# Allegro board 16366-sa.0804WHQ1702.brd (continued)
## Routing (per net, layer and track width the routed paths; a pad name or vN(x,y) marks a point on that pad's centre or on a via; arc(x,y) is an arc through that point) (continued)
RESET_P12V_MB_IN: length 3.8
  TOP w0.178: U1.3 19.66,18.65 C19.1 R2.1 19.06,17.63 R1.2
RSVD0: length 11.3
  TOP w0.178: GF1.B30 42.65,7.97 45.12,12.27 TP6.1
RSVD1: length 12
  TOP w0.178: v1(31.65,8.9) 31.65,9.61 TP7.1
  BOTTOM w0.178: GF1.A19 v1(31.65,8.9)
S0_PCIE_SMCLK: length 26.4
  TOP w0.178: CN1.B5 26.29,29.78 26.29,29.37 26.09,29.17 20.75,29.17 19.43,27.85 17.2,27.85 14.81,30.23 14.81,40.19 15.68,41.06 15.68,41.46 15.68,41.62 15.67,41.64 15.97,41.94 RE1.1
S0_PCIE_SMDAT: length 27.8
  TOP w0.178: RE7.1 14.94,41.93 15.24,41.63 15.24,41.46 15.24,41.24 14.38,40.37 14.38,30.05 17.02,27.41 19.61,27.41 20.93,28.74 26.85,28.74 27.09,28.49 CN1.B6
S0_SMB_ALERT_B12_N: length 3.5
  TOP w0.178: RE4.1 CN1.B12
S0_SMB_CLK_A32: length 19
  TOP w0.178: CN1.A32 55.44,34.82 55.44,35.22 55.11,35.55 39.68,35.55 39.09,36.14 39.09,36.49 38.8,36.79 RE2.2
S0_SMB_DAT_A33: length 20.9
  TOP w0.178: CN1.A33 56.09,35.18 55.29,35.98 39.86,35.98 39.53,36.32 39.53,36.49 39.82,36.79 RE3.2
S1_PCIE_SMCLK: length 11.5
  TOP w0.178: CN2.B5 26.09,48.74 24.63,47.28 21.72,47.28 20.6,48.39 18.36,48.39 RE6.1
S1_PCIE_SMDAT: length 10.5
  TOP w0.178: RE8.1 18.06,47.71 18.32,47.96 20.42,47.96 21.54,46.85 24.81,46.85 26.4,48.43 26.94,48.98 27.09,48.98 CN2.B6
S1_SMB_ALERT_B12_N: length 6.5
  TOP w0.178: RE5.1 36.64,43.36 36.64,45.99 35.09,47.54 CN2.B12
S1_SMB_CLK_A32: length 32.9
  TOP w0.178: RE9.2 39.13,41.41 39.13,42.08 37.92,43.29 37.92,45.68 35.87,47.73 35.87,49.59 36.88,50.6 36.88,51.74 37.56,52.42 38.29,52.42 38.85,52.98 38.85,53.97 39.57,54.68 54.3,54.68 55.09,55.47 CN2.A32
S1_SMB_DAT_A33: length 33.2
  TOP w0.178: CN2.A33 56.09,53.47 55.31,54.25 54.48,54.25 54.48,54.25 39.75,54.25 39.29,53.79 39.29,52.8 38.47,51.99 37.74,51.99 37.31,51.56 37.31,50.42 36.3,49.41 36.3,47.91 38.35,45.85 38.35,43.47 39.56,42.26 39.56,41.41 RE10.2
S2_PCIE_SMCLK: length 5.3
  TOP w0.178: CN3.B5 26.09,69.59 25.77,69.27 25.77,67.92 25.42,67.57 RE12.1
S2_PCIE_SMDAT: length 3.5
  TOP w0.178: CN3.B6 27.09,69.97 26.2,69.09 26.2,67.92 26.56,67.57 RE13.1
S2_SMB_ALERT_B12_N: length 5.8
  TOP w0.178: RE11.1 37.3,66.62 35.09,68.83 CN3.B12
S2_SMB_CLK_A32: length 39.1
  TOP w0.178: CN3.A32 55.09,75.91 54.86,75.68 37.6,75.68 36.87,74.95 36.87,71.62 35.91,70.66 35.91,69.03 43.91,61.03 43.91,59.06 RE14.2
S2_SMB_DAT_A33: length 39.1
  TOP w0.178: RE15.2 44.34,59.14 44.34,61.2 36.34,69.21 36.34,70.48 37.3,71.44 37.3,74.77 37.78,75.25 55.32,75.25 56.09,74.47 CN3.A33
SLOT0_CONFIG: length 22.9
  TOP w0.178: v1(70.51,22.69) 70.99,23.17 R33.1
  BOTTOM w0.178: GF1.A50 62.65,7.95 67.01,14.18 v2(68.83,20.53) 69.96,22.14 v1(70.51,22.69)
SLOT0_ID_0: length 10.3
  TOP w0.178: CN1.A19 41.87,32.47 40.83,31.44 39.87,31.44 38.9,30.47 38.9,29.48 39.92,28.47 39.92,25.56 R7.1
SLOT0_ID_1: length 3.2
  TOP w0.178: R8.2 53.09,25.04 CN1.B30
SLOT1_CONFIG: length 12.1
  TOP w0.178: v1(94.89,9.58) 95.08,9.77 v2(95.08,13.75) R35.1
  BOTTOM w0.178: GF1.A83 95.65,7.09 94.89,7.85 v1(94.89,9.58)
SLOT1_ID_0: length 10.1
  TOP w0.178: R10.1 40.07,47.35 40.07,49.5 39.13,50.44 39.13,51.43 39.95,52.24 40.86,52.24 42.09,53.47 CN2.A19
SLOT1_ID_1: length 3.4
  TOP w0.178: CN2.B30 53.1,48.96 53.1,46.94 R9.2
SLOT2_ID_0: length 10.7
  TOP w0.178: R12.1 40.1,69.73 40.1,70.53 39.19,71.44 39.19,72.41 41.26,74.47 42.09,74.47 CN3.A19
SLOT2_ID_1: length 4.2
  TOP w0.178: CN3.B30 53.09,69.56 R11.2

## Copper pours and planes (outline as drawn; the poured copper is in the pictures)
GND on TOP: 25.75,41.34 25.75,37.79 25.54,37.58 22.38,37.58 21.95,38.02 21.95,41.26 22.25,41.56 25.53,41.56
GND on TOP: 33.77,35.7 33.06,36.42 33.06,38.02 32.66,38.42 32.4,38.42 32.38,38.4 32.05,38.73 32.05,41.09 32.49,41.53 32.52,41.53 32.53,41.52 34.28,41.52 34.89,40.91 34.89,36.03 34.56,35.7 ; 5 cut-outs
GND on TOP: 19.76,62.82 21.21,61.37 21.21,59.52 19.76,58.07 16.69,58.07 16.21,58.55 16.21,62.52 16.51,62.82
GND on TOP: 107.98,61.48 107.68,61.78 107.68,63.23 107.45,63.46 107.12,63.46 106.65,63.93 106.65,69.5 106.18,69.96 106.18,70.45 106.54,70.8 107.25,70.8 108.06,71.61 109.03,71.61 109.91,70.73 109.91,63.66 109.46,63.21 109.46,61.66 109.28,61.48
GND on TOP: 113.33,45.6 112.67,46.26 112.67,47.61 114.15,49.08 114.15,54.72 114.22,54.8 116.66,54.8 116.94,54.52 116.94,46.08 116.46,45.6 ; 1 cut-out
GND on TOP: 35.88,58.59 35.19,59.27 35.19,62.07 35.6,62.48 37.56,62.48 37.57,62.47 38.08,62.47 39.04,61.5 39.04,59.74 37.89,58.59
GND on TOP: 26.69,57.12 26.31,57.49 26.31,64.39 27.02,65.09 27.02,65.32 27,65.33 27,67.14 27.45,67.59 28.49,67.59 28.64,67.44 28.64,65.85 28.03,65.24 28.03,65.22 27.91,65.09 27.91,57.45 27.58,57.12 ; 11 cut-outs
GND on TOP: 109.83,61.83 110.59,61.83 110.72,61.7 110.72,61.02 110.97,60.76 118.82,60.76 118.87,60.71 118.87,59.09 116.97,57.18 104.83,57.18 104.6,57.41 104.6,58.15 105.03,58.58 109.25,58.58 109.86,59.19 109.86,61.4 109.8,61.45 109.8,61.81
GND on L2GND: outline of 189 points within 0.76,2.54 138.54,77.74
GND on L3: 11.82,18.81 11.79,18.85 11.79,23.73 10.77,24.75 9.73,24.75 8.28,26.2 8.28,27.9 6.93,29.24 5.05,29.24 3.71,27.9 3.71,26.02 2.44,24.75 1.02,24.75 0.79,24.98 0.79,77.21 1.19,77.62 18.68,77.62 19.25,77.05 19.25,58.25 18.67,57.67 4.34,57.67 2.82,56.14 2.82,42.25 19.09,25.98 19.09,14.22 20.06,13.24 25.83,13.24 33.21,20.63 33.21,43.83 33.8,44.42 131.86,44.42 138.32,44.42 138.51,44.23 138.51,25.41 138.07,24.98 136.88,24.98 135.64,26.22 135.64,27.95 134.32,29.27 132.36,29.27 130.99,27.9 130.99,25.97 129.77,24.75 128.55,24.75 127.53,23.73 127.53,18.63 127.51,18.61 127.51,2.85 127.2,2.55 25.02,2.55 24.87,2.7 24.87,8.19 23.88,9.18 22.43,9.18 21.44,8.19 21.44,2.85 21.13,2.55 11.91,2.55 11.82,2.64
GND on L4: 24.86,2.54 24.86,7.45 24.86,7.51 24.86,7.67 24.92,7.73 24.92,22.35 27.97,25.41 35.49,25.41 36.4,26.32 36.4,28.25 37.47,29.31 37.47,32.87 38.51,33.91 38.51,35.16 39.27,35.92 111.77,35.92 117.68,41.84 117.68,77.74 138.3,77.74 138.47,77.67 138.54,77.5 138.54,24.96 138.47,24.79 138.3,24.72 137.04,24.72 136.46,24.87 136.01,25.27 135.93,25.39 135.84,25.51 135.63,25.88 135.56,26.29 135.56,26.96 135.56,27.03 135.56,27.28 135.54,27.3 133.3,29.22 131.06,27.3 131.04,27.28 131.04,27.03 131.04,26.96 131.04,26.29 130.97,25.88 130.76,25.51 130.67,25.39 130.59,25.27 130.14,24.87 129.56,24.72 129.3,24.72 129.24,24.72 128.98,24.72 128.95,24.69 128.05,24.21 127.57,23.31 127.54,23.28 127.54,23.02 127.54,22.96 127.54,2.54
GND on L4: 10.62,24.61 10.49,24.65 10.35,24.69 10.32,24.72 10.06,24.72 10,24.72 9.74,24.72 9.16,24.87 8.71,25.27 8.63,25.39 8.54,25.51 8.33,25.88 8.26,26.29 8.26,26.96 8.26,27.03 8.26,27.28 8.24,27.3 6,29.22 3.76,27.3 3.74,27.28 3.74,27.03 3.74,26.96 3.74,26.29 3.67,25.88 3.46,25.51 3.37,25.39 3.29,25.27 2.84,24.87 2.26,24.72 1,24.72 0.83,24.79 0.76,24.96 0.76,77.5 0.83,77.67 1,77.74 25.01,77.74 25.78,76.96 25.78,36.36 14.93,36.36 10.62,32.04
GND on L5GND: outline of 197 points within 0.76,2.54 138.54,77.74
P3V3 on TOP: 27.05,42 31.61,42 32.02,41.6 32.02,38.47 31.97,38.42 32.48,37.91 32.55,37.91 32.55,36.59 32.12,36.16 27.36,36.16 26.67,36.85 26.67,41.62 ; 6 cut-outs
P3V3 on TOP: 28.31,57.62 28.31,65.28 28.46,65.42 28.89,65.42 29.15,65.68 29.15,67.2 29.26,67.3 30.75,67.3 30.95,67.1 30.95,62.63 31.26,62.32 33.8,62.32 34.26,61.87 34.26,58.6 33.15,57.49 28.44,57.49 ; 11 cut-outs
P3V3 on TOP: 106.12,45.73 98.27,53.58 98.27,57.82 98.96,58.5 103.45,58.5 104.04,57.92 104.04,57.03 104.57,56.5 114.83,56.5 115.01,56.32 115.01,55.18 114.17,55.18 113.77,54.77 113.77,49.54 111.96,47.73 111.96,46.29 111.4,45.73 ; 2 cut-outs
P3V3 on L4: 27.97,26.17 26.54,27.6 26.54,35.74 26.62,35.82 26.62,36.13 26.54,36.21 26.54,77.12 27.16,77.74 116.92,77.74 116.92,42.15 111.45,36.69 38.96,36.69 37.74,35.47 37.74,34.23 36.7,33.19 36.7,29.63 35.64,28.56 35.64,26.63 35.17,26.17
P3V3_AUX on TOP: 20.29,6.17 20.09,6.37 20.09,7.29 19.37,8.01 19.37,12.95 21.46,15.04 23.57,15.04 24.19,14.43 24.19,13.19 21.36,10.36 21.36,9.36 21.33,9.33 21.33,6.63 20.87,6.17
P3V3_AUX on TOP: 29.81,22.22 29.58,22.45 29.58,23.89 30.19,24.5 30.19,26.92 29.94,27.17 29.94,28.83 30.28,29.17 32.28,29.17 32.82,28.63 32.82,22.69 32.34,22.22 ; 2 cut-outs
P3V3_AUX on BOTTOM: 15.79,46.55 15.64,46.7 15.64,54.65 19.46,58.48 25.1,58.48 27.44,60.81 27.44,66.6 29.23,68.39 32.22,68.39 32.4,68.22 32.4,66.31 30.24,64.15 30.24,59.91 27.63,57.29 27.61,57.29 26.69,56.37 22,56.37 18.33,52.7 18.33,47.08 17.8,46.55
P3V3_AUX on L3: 20.25,13.52 19.52,14.24 19.52,26.36 3.43,42.45 3.43,55.71 4.5,56.78 18.75,56.78 19.13,56.4 19.13,47.52 20.37,46.27 25.26,46.27 26.89,47.9 26.9,47.9 29.38,50.38 32.58,50.38 32.91,50.05 32.91,46.07 32.91,33.38 32.73,33.21 32.73,20.49 25.76,13.52
P3V3_LL on TOP: 99.6,59.09 99.55,59.14 97.72,59.14 96.83,60.03 96.83,64.1 96.84,64.1 96.84,65.07 97.41,65.64 100.18,65.64 100.28,65.54 100.28,64.57 100.63,64.22 103.38,64.22 104.75,65.59 104.75,66.53 104.99,66.76 106.32,66.76 106.32,63.52 106.51,63.33 106.51,59.68 105.93,59.09 ; 5 cut-outs
P3V3_VIN on TOP: 109.69,62.19 109.69,62.65 110.21,63.17 110.21,63.18 110.29,63.25 110.29,66.69 110.39,66.79 116.39,66.79 116.77,67.17 117.79,67.17 118.25,66.71 118.25,63.37 118.88,62.74 118.88,61.25 118.68,61.04 111.02,61.04 110.92,61.15 110.92,61.88 110.72,62.09 109.79,62.09 ; 2 cut-outs
P12V on TOP: 117.83,44.18 117.45,44.56 117.45,56.42 119.51,58.48 119.51,63.03 118.77,63.76 118.77,66.81 119.53,67.57 119.53,68.33 119.18,68.69 119.18,69.43 119.38,69.63 122.68,69.63 123.29,69.02 123.29,44.56 122.91,44.18 ; 5 cut-outs
P12V on TOP: 18.69,47.82 16.81,49.7 16.81,57.13 17.46,57.78 19.85,57.78 21.46,59.39 21.46,61.58 19.38,63.66 16.78,63.66 16.7,63.74 16.7,67.1 16.33,67.47 16.33,68.21 16.61,68.49 16.92,68.49 17.45,69.02 18.54,69.02 18.95,69.43 18.95,72.75 19.38,73.19 24.74,73.19 25.04,72.88 25.04,68.38 24.21,67.55 23.31,67.55 23.05,67.29 23.05,64.98 23.89,64.14 25.65,64.14 26.01,63.79 26.01,57.04 25.32,56.35 25.32,50.21 24.35,49.24 24.35,48.35 23.82,47.82 ; 31 cut-outs
P12V on L3: 25.19,46.78 20.9,46.78 19.81,47.86 19.81,77.5 20.04,77.73 138.2,77.73 138.53,77.4 138.53,45.57 137.8,44.85 34.66,44.85 33.44,46.07 33.44,48.38 33.47,48.4 33.47,50 32.7,50.77 29.18,50.77
P12V_MB on TOP: 18.84,34.42 18.84,30 18.2,29.35 17.13,29.35 16.97,29.52 16.97,34.5 17.3,34.83 18.44,34.83 ; 8 cut-outs
P12V_MB on TOP: 12.15,8.94 12.45,9.25 14.39,9.25 14.69,8.96 14.69,6.95 13.96,6.22 13.96,2.7 13.84,2.58 11.88,2.58 11.88,2.58 11.63,2.58 11.51,2.7 11.51,5.95 12.15,6.59
P12V_MB on BOTTOM: 13.96,2.89 13.73,2.66 12.5,2.66 12.31,2.85 12.31,6.57 12.67,6.93 12.67,8.79 12.85,8.97 14.06,8.97 14.06,8.97 14.54,8.97 14.71,8.8 14.71,7.17 13.96,6.43
P12V_MB on L4: 11.76,2.54 11.76,22.96 11.76,23.02 11.76,23.28 11.73,23.31 11.6,23.7 11.38,24.06 11.38,31.73 15.25,35.59 25.78,35.59 25.78,27.28 27.27,25.79 24.16,22.67 24.16,8.84 22.53,9.05 21.47,7.8 21.44,7.77 21.44,7.51 21.44,7.45 21.44,2.54

Small or netless copper shapes (teardrops, artwork), in the pictures only: 2 on TOP, 2 on BOTTOM

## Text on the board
Ref Des/Silkscreen Bottom: FB PN | PN Label | SN Label
Ref Des/Silkscreen Top: PCIE X8 SLOT2 | PCIE X8 SLOT3 | PCIE X8 SLOT4 | LBC 3 slot PCIE riser | 16366-SA | B48.01701.00SA | MADE IN TAIWAN
User.31: ByImpedance:50.0@_REF_L1=("7.0(L1)")|_REF_L5GND=("nil(L5GND)")|_REF_L6=("7.0(L6)")|Type="SE"|_REF_L4=("5.0(L4)")|_REF_L3=("5.0(L3)")|imp="50.0"|_REF_L2GND=("nil(L2GND)") | ByImpedance:85.0@_REF_L1=("7.0/5.0(L1)")|_REF_L5GND=("nil(L5GND)")|_REF_L6=("7.0/5.0(L6)")|Type="DP"|_REF_L4=("5.0/6.5(L4)")|_REF_L3=("5.0/6.5(L3)")|imp="85.0"|_REF_L2GND=("nil(L2GND)") | LayerIndex:nil | Source:Wiwynn_15703-SA_Leopard_BW_3x8_PCIe_Riser_6L_Stackup_RPT_20151015.xlsx | artWorks:("_REF_L3" "_REF_L5GND" "_REF_L4" "_REF_L6" "_REF_L2GND" "_REF_L1") | gtImpOutlineUsed:BOARD GEOMETRY/PANEL_OUTLINE
User.32: Board Accuracy Check,Nov 19 16:36:07 2015,Passed | Dummy-Static-No Shape On Layer Check,Nov 19 16:36:07 2015,Passed | Split Plane Check,Nov 19 16:36:06 2015,Passed
User.34: This gerber is just for your reference to find the DP impedance traces in layer L1. | DP IMPEDANCE TABLE: L1 | * - Denotes that WIDTH | is NOT used in this layer | inside board outline. | IMP(Ohm) | 85.0 | WIDTH(mils) | 7.0/5.0 | TYPE | DP
User.36: This gerber is just for your reference to find the SE impedance traces in layer L1. | SE IMPEDANCE TABLE: L1 | * - Denotes that WIDTH | is NOT used in this layer | inside board outline. | IMP(Ohm) | 50.0 | WIDTH(mils) | 7.0 | TYPE | SE
User.38: This gerber is just for your reference to find the DP impedance traces in layer L3. | DP IMPEDANCE TABLE: L3 | * - Denotes that WIDTH | is NOT used in this layer | inside board outline. | IMP(Ohm) | 85.0 | WIDTH(mils) | *5.0/6.5 | TYPE | DP
User.40: This gerber is just for your reference to find the SE impedance traces in layer L3. | SE IMPEDANCE TABLE: L3 | * - Denotes that WIDTH | is NOT used in this layer | inside board outline. | IMP(Ohm) | 50.0 | WIDTH(mils) | *5.0 | TYPE | SE
User.42: This gerber is just for your reference to find the DP impedance traces in layer L4. | DP IMPEDANCE TABLE: L4 | * - Denotes that WIDTH | is NOT used in this layer | inside board outline. | IMP(Ohm) | 85.0 | WIDTH(mils) | *5.0/6.5 | TYPE | DP
User.44: This gerber is just for your reference to find the SE impedance traces in layer L4. | SE IMPEDANCE TABLE: L4 | * - Denotes that WIDTH | is NOT used in this layer | inside board outline. | IMP(Ohm) | 50.0 | WIDTH(mils) | *5.0 | TYPE | SE
User.45: P12V_MB | GND | P3V3 | Note:Refer to DRILL layer for ELLIPSE drill direction | FIGURE | SIZE | 12.0 | 16.0 | 28.0 | 71.0 | 139.0 | 86.0 | 93.0 | DRILL CHART: TOP to BOTTOM | ALL UNITS ARE IN MILS | PLATED | NON-PLATED | QTY | 332 | 48 | 294 | 4 | 2 | 5 | 6 | This gerber is just for your reference to find the DP impedance traces in layer L2GND. | This gerber is just for your reference to find the DP impedance traces in layer L5GND. | This gerber is just for your reference to find the DP impedance traces in layer L6. | This gerber is just for your reference to find the SE impedance traces in layer L2GND. | This gerber is just for your reference to find the SE impedance traces in layer L5GND. | This gerber is just for your reference to find the SE impedance traces in layer L6. | DP IMPEDANCE TABLE: L2GND | DP IMPEDANCE TABLE: L5GND | DP IMPEDANCE TABLE: L6 | SE IMPEDANCE TABLE: L2GND | SE IMPEDANCE TABLE: L5GND | SE IMPEDANCE TABLE: L6 | * - Denotes that WIDTH | is NOT used in this layer | inside board outline. | Model | LBW 3 slot PCIE riser 6L | PCB_NO | 15703 | VER. | SA | Layer | DRILL | L1 | L2GND | L3 | TMASK | TPLACE | TSILK | TSMD | IMP(Ohm) | 50.0 | 85.0 | Designer | LIZ LIN | WIDTH(mils) | *nil | 7.0 | 7.0/5.0 | Date | 11/19/2015 | TYPE | DP | SE | BMASK | BPLACE | BSILK | BSMD | L4 | L5GND | L6
